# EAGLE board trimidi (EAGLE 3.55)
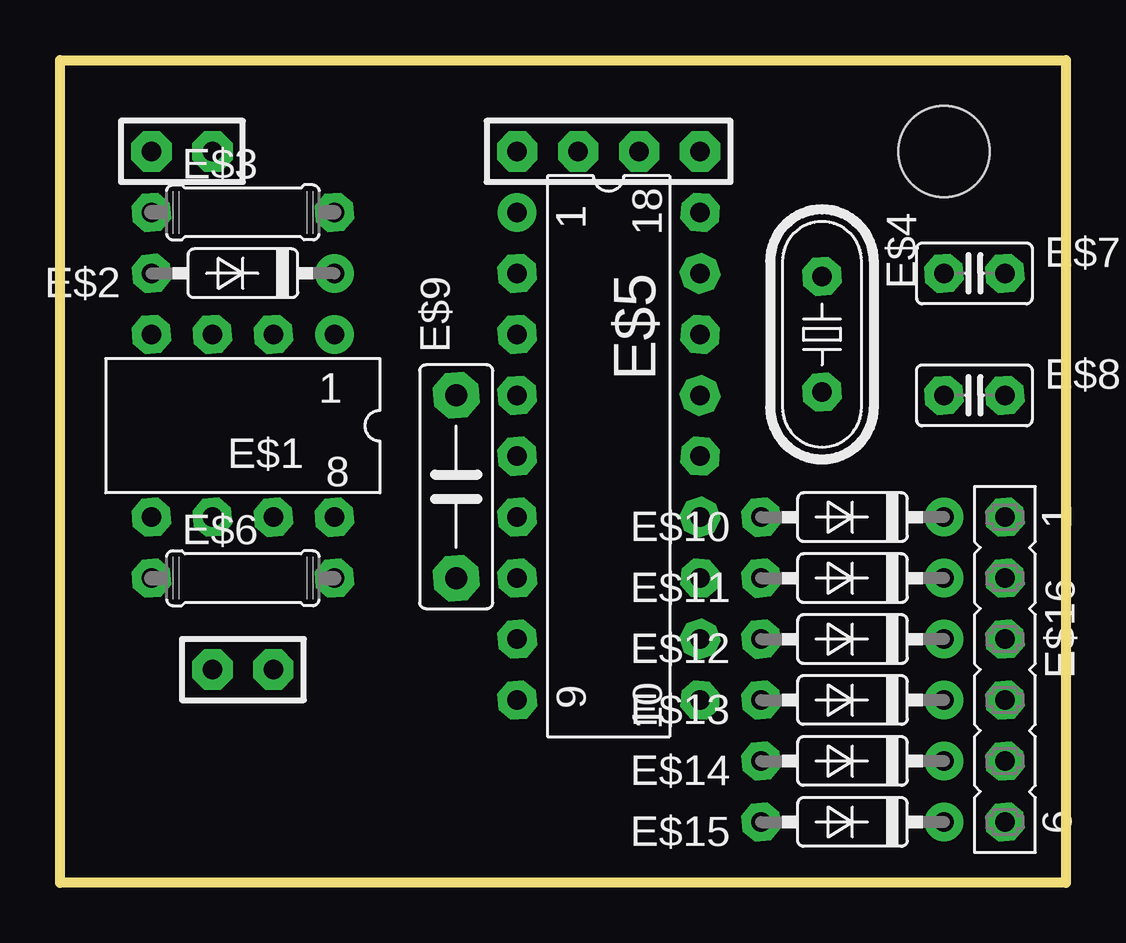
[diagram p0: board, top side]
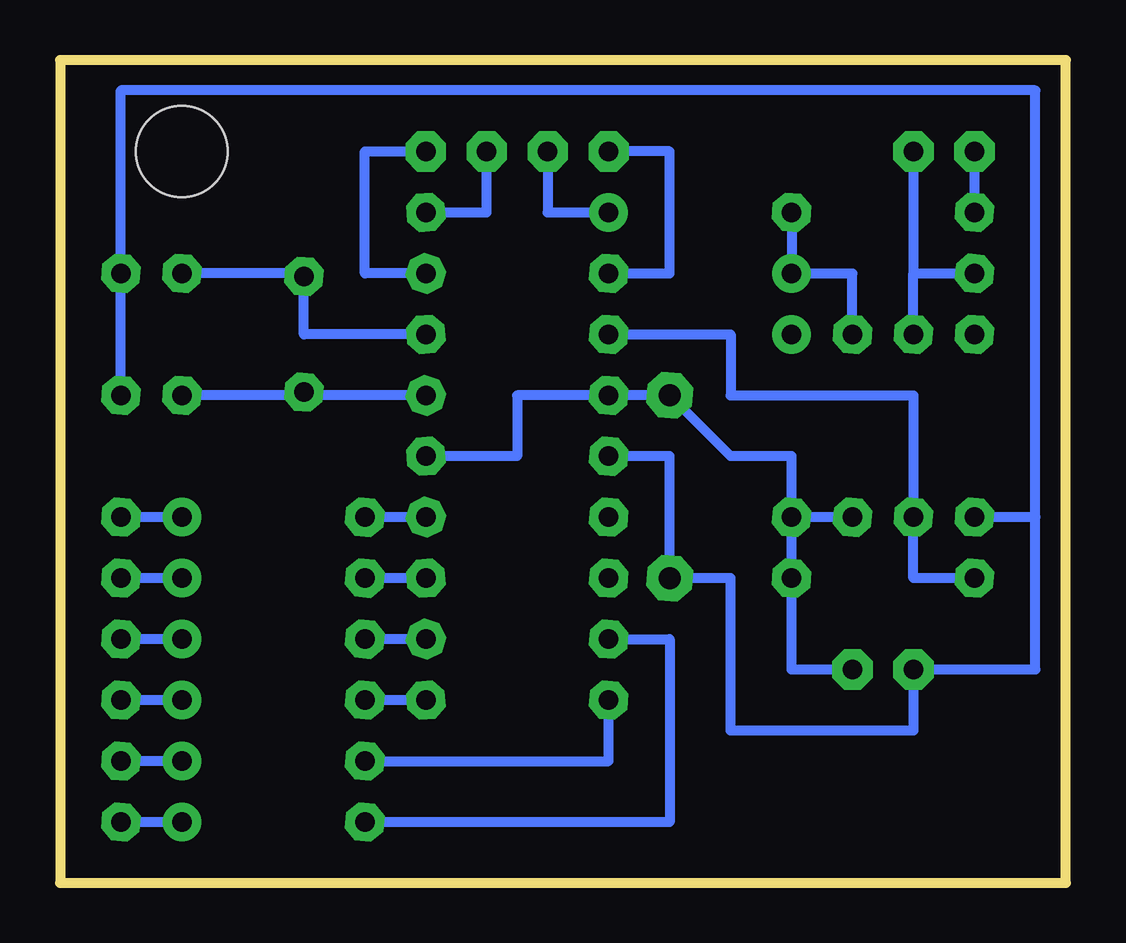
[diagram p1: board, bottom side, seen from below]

Size 41.91 x 34.29 mm. Coordinates in mm from the lower left corner, seen from the top.
Outline: 0,34.29 41.91,34.29 41.91,0 0,0 0,34.29
Copper layers used: Bottom
Holes 3.81 mm at 36.83,30.48

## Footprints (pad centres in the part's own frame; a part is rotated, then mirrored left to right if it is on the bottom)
L08 = drill 0.813 pad 1.6 round:  -3.81,-3.81 | drill 0.813 pad 1.6 octagon:  -1.27,-3.81;  1.27,-3.81;  3.81,-3.81;  3.81,3.81;  1.27,3.81;  -1.27,3.81;  -3.81,3.81
35-7 = drill 0.813 pad 1.6 round:  -3.81,0 | drill 0.813 pad 1.6 octagon:  3.81,0
07/7 = drill 0.813 pad 1.6 octagon:  -3.81,0;  3.81,0
49/S = drill 0.813 pad 1.6 octagon:  -2.413,0;  2.413,0
L18 = drill 0.813 pad 1.6 round:  -10.16,-3.81 | drill 0.813 pad 1.6 octagon:  -7.62,-3.81;  -5.08,-3.81;  -2.54,-3.81;  0,-3.81;  2.54,-3.81;  5.08,-3.81;  7.62,-3.81;  10.16,-3.81;  10.16,3.81;  7.62,3.81;  5.08,3.81;  2.54,3.81;  0,3.81;  -2.54,3.81;  -5.08,3.81;  -7.62,3.81;  -10.16,3.81
,5-2 = drill 0.813 pad 1.6 octagon:  -1.27,0;  1.27,0
,5B3 = drill 0.914 pad 1.905 octagon:  -3.81,0;  3.81,0
06 = drill 0.813 pad 1.6 octagon:  -6.35,0;  -3.81,0;  -1.27,0;  1.27,0;  3.81,0;  6.35,0

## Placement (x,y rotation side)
E$1  6N137  [L08]  7.62,19.05 180 top
E$2  1N4148  [35-7]  7.62,25.4 180 top
E$3  220  [07/7]  7.62,27.94 0 top
E$4  8MHz  [49/S]  31.75,22.86 270 top
E$5  PIC16F84/10MHz  [L18]  22.86,17.78 270 top
E$6  360  [07/7]  7.62,12.7 0 top
E$7  33p  [,5-2]  38.1,25.4 0 top
E$8  33p  [,5-2]  38.1,20.32 0 top
E$9  0.1  [,5B3]  16.51,16.51 90 top
E$10  1N4148  [35-7]  33.02,15.24 180 top
E$11  1N4148  [35-7]  33.02,12.7 180 top
E$12  1N4148  [35-7]  33.02,10.16 180 top
E$13  1N4148  [35-7]  33.02,7.62 180 top
E$14  1N4148  [35-7]  33.02,5.08 180 top
E$15  1N4148  [35-7]  33.02,2.54 180 top
E$16  [06]  39.37,8.89 270 top

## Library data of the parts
E$1 = optocpl
E$2 E$10-E$15 = diode
E$3 E$6 = r
E$4 = quartz
E$5 = pic
E$7-E$9 = cap
E$16 = con-lsta

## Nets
S$1: E$1. E$5. E$6.
S$2: E$1. E$5. E$6. E$9.
S$3: E$14. E$16.
S$4: E$5. E$7.
S$5: E$1. E$2. E$3.
S$6: E$5. E$10.
S$7: E$5. E$11.
S$8: E$5. E$12.
S$9: E$5. E$13.
S$10: E$5. E$14.
S$11: E$5. E$15.
S$12: E$10. E$16.
S$13: E$11. E$16.
S$14: E$12. E$16.
S$15: E$13. E$16.
S$16: E$15. E$16.
S$17: E$5. E$8.
S$18: E$1. E$5. E$7. E$8. E$9.
S$20: E$3.
S$21: E$1. E$2.
S$22: E$5.
S$23: E$5.
S$24: E$5.
S$25: E$5.

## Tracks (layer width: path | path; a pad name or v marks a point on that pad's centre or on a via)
S$1
  Bottom 0.406: 3.81,12.7 6.35,12.7 6.35,15.24 6.35,20.32 13.97,20.32 13.97,22.86 19.05,22.86
S$2  (via drill 0.81 pad 1.68)
  Bottom 0.406: 26.67,17.78 22.86,17.78 22.86,20.32 19.05,20.32 E$9. 13.97,17.78 11.43,17.78 E$1. | v8.89,8.89 11.43,8.89 E$6. E$1. | 8.89,15.24 E$1.
S$3
  Bottom 0.406: 36.83,5.08 39.37,5.08
S$4
  Bottom 0.406: 26.67,22.86 31.75,22.86 31.75,25.4 36.83,25.4
S$5
  Bottom 0.406: 8.89,22.86 8.89,25.4 11.43,25.4 E$3.
S$6
  Bottom 0.406: 26.67,15.24 E$10.
S$7
  Bottom 0.406: 26.67,12.7 E$11.
S$8
  Bottom 0.406: 26.67,10.16 E$12.
S$9
  Bottom 0.406: 26.67,7.62 E$13.
S$10
  Bottom 0.406: E$14. 19.05,5.08 19.05,7.62
S$11
  Bottom 0.406: 19.05,10.16 16.51,10.16 16.51,2.54 E$15.
S$12
  Bottom 0.406: 36.83,15.24 39.37,15.24
S$13
  Bottom 0.406: 36.83,12.7 39.37,12.7
S$14
  Bottom 0.406: 36.83,10.16 39.37,10.16
S$15
  Bottom 0.406: 36.83,7.62 39.37,7.62
S$16
  Bottom 0.406: 36.83,2.54 E$16.
S$17
  Bottom 0.406: 26.67,20.32 36.83,20.32
S$18  (via drill 0.81 pad 1.68)
  Bottom 0.406: E$8. E$7. 39.37,33.02 1.27,33.02 1.27,15.24 | 19.05,17.78 16.51,17.78 16.51,12.7 13.97,12.7 13.97,6.35 6.35,6.35 v6.35,8.89 1.27,8.89 1.27,15.24 | 1.27,15.24 3.81,15.24
S$20  (via drill 0.81 pad 1.68)
  Bottom 0.406: v3.81,30.48 3.81,27.94
S$21  (via drill 0.81 pad 1.68)
  Bottom 0.406: 6.35,22.86 6.35,25.4 | 6.35,25.4 E$2. | v6.35,30.48 6.35,25.4
S$22  (via drill 0.81 pad 1.68)
  Bottom 0.406: 26.67,25.4 29.21,25.4 29.21,30.48 v26.67,30.48
S$23  (via drill 0.81 pad 1.68)
  Bottom 0.406: E$5. 24.13,27.94 v24.13,30.48
S$24  (via drill 0.81 pad 1.68)
  Bottom 0.406: v21.59,30.48 21.59,27.94 19.05,27.94
S$25  (via drill 0.81 pad 1.68)
  Bottom 0.406: 19.05,25.4 16.51,25.4 16.51,30.48 v19.05,30.48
